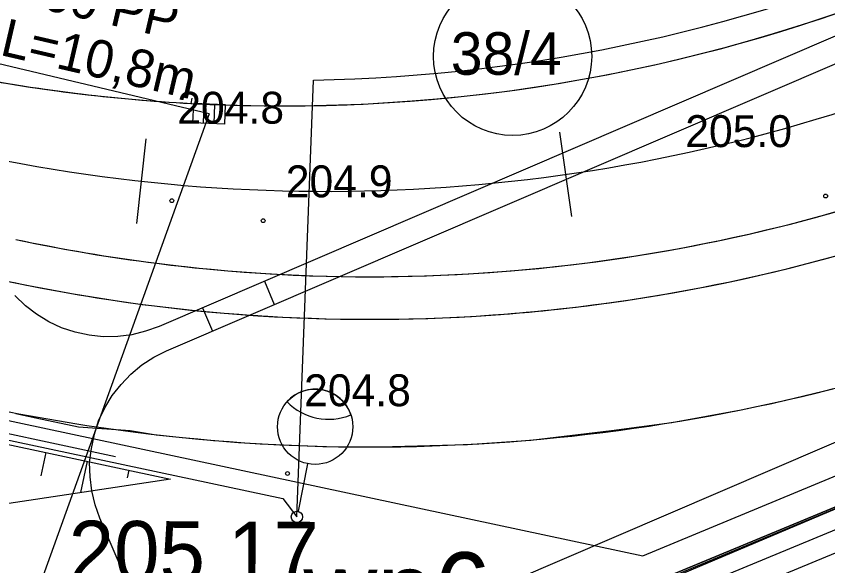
# Model space of a CAD drawing. Extents: x 6512606 to 6513347, y 6022524 to 6022728.
# Drawn here: x 6512813.48 to 6512832.56, y 6022573.02 to 6022585.94 of the extents above; entities that cross this region are included whole.
import ezdxf

# ---------------------------------------------------------------- set-up
doc = ezdxf.new("R2010")
doc.units = 0
for name, color, linetype in [('20', 7, 'Continuous'), ('211-numer działki ewidencyjnej', 7, 'Continuous'), ('217-kontur klasyfikacyjny', 7, 'Continuous'), ('218-kontur użytku gruntowego', 7, 'Continuous'), ('219-działka ewidencyjna', 7, 'Continuous'), ('4', 7, 'Continuous'), ('6', 7, 'Continuous'), ('Default', 7, 'Continuous'), ('E_OSW_KABLE', 7, 'Continuous'), ('E_OSW_LAMPA', 7, 'Continuous'), ('kolor_kostka_bet', 7, 'Continuous'), ('kolor_sc_rowerowa', 7, 'Continuous'), ('Level 47', 7, 'Continuous'), ('Level 60', 7, 'Continuous'), ('maxp_bariera_ochronna', 7, 'Continuous'), ('maxp_inst_energ', 7, 'Continuous'), ('maxp_kan_deszczowa', 7, 'Continuous'), ('maxp_kratki', 7, 'Continuous'), ('maxp_krawężnik', 7, 'Continuous'), ('maxp_obrzeże', 7, 'Continuous'), ('maxp_os', 7, 'Continuous'), ('maxp_ramka_2', 7, 'Continuous'), ('maxp_skarpa', 7, 'Continuous'), ('ogrodzenie trwałe', 7, 'Continuous'), ('pikieta naturalna', 7, 'Continuous'), ('pikieta naturalna-Atr2', 7, 'Continuous'), ('punkt wysokościowy naturalny', 7, 'Continuous'), ('punkt wysokościowy naturalny-Atr2', 7, 'Continuous'), ('urządzenie techniczne projektowane lub w budowie (sieć kanalizacyjna) - powierzchnia - ob. projektowany', 7, 'Continuous')]:
    doc.layers.add(name, color=color, linetype=linetype)

# ---------------------------------------------------------------- blocks, each defined once
blk = doc.blocks.new('PW01')
at = {"layer": 'Default'}
blk.add_circle((0, 0), 0.45, dxfattribs=at)

msp = doc.modelspace()

# ---------------------------------------------------------------- linework, layer by layer
at = {"layer": '20'}
msp.add_line((6512818.017, 6022583.64), (6512813.949, 6022572.326), dxfattribs=at)
at = {"layer": '217-kontur klasyfikacyjny'}
msp.add_lwpolyline([(6512825.22, 6022571.29), (6512855.78, 6022583.95)], dxfattribs=at)
at = {"layer": '218-kontur użytku gruntowego'}
for points in [[(6512825.22, 6022571.29), (6512855.78, 6022583.95)], [(6512855.78, 6022583.95), (6512825.22, 6022571.29)]]:
    msp.add_lwpolyline(points, dxfattribs=at)
at = {"layer": '219-działka ewidencyjna'}
msp.add_lwpolyline([(6512825.22, 6022571.29), (6512855.78, 6022583.95)], dxfattribs=at)
at = {"layer": '4'}
msp.add_lwpolyline([(6512825.22, 6022571.29), (6512855.78, 6022583.95)], dxfattribs=at)
at = {"layer": '6'}
msp.add_circle((6512825.152, 6022584.993), 1.859, dxfattribs=at)
at = {"layer": 'E_OSW_KABLE'}
msp.add_line((6512820.082, 6022574.17), (6512820.469, 6022584.435), dxfattribs=at)
msp.add_lwpolyline([(6512791.895, 6022580.179), (6512792.146, 6022580.477), (6512819.749, 6022574.599), (6512820.082, 6022574.17)], dxfattribs=at)
msp.add_arc((6512819.75, 6022623.828), 39.4, 271.0457, 293.7363, dxfattribs=at)
at = {"layer": 'E_OSW_LAMPA'}
msp.add_line((6512820.334, 6022575.413), (6512820.109, 6022574.3), dxfattribs=at)
for centre, radius in [((6512820.511, 6022576.288), 0.885), ((6512820.082, 6022574.17), 0.132)]:
    msp.add_circle(centre, radius, dxfattribs=at)
for centre, radius, start, end in [((6512820.511, 6022576.288), 0.885, 18.4482, 138.4482), ((6512820.825, 6022577.825), 1.362, 224.2189, 292.6775)]:
    msp.add_arc(centre, radius, start, end, dxfattribs=at)
at = {"layer": 'kolor_kostka_bet'}
msp.add_lwpolyline([(6512773.05, 6022582.65), (6512780.7, 6022581.02), (6512806.2, 6022572.11), (6512806.62, 6022563.51), (6512855.78, 6022583.95)], dxfattribs=at)
msp.add_lwpolyline([(6512773.05, 6022582.65), (6512780.7, 6022581.02), (6512806.2, 6022572.11), (6512806.62, 6022563.51), (6512855.78, 6022583.95)], dxfattribs=at)
for centre, radius, start, end in [((6512819.75, 6022623.828), 40, 270.7527, 293.397), ((6512819.75, 6022623.828), 40, 270.7527, 293.397), ((6512819.75, 6022623.828), 40, 257.9783, 263.418), ((6512819.75, 6022623.828), 40, 258.9864, 263.418), ((6512819.75, 6022623.828), 40, 263.418, 270.7527), ((6512819.75, 6022623.828), 40, 263.418, 270.7527), ((6512821.802, 6022619.813), 40, 257.9783, 293.3967), ((6512821.802, 6022619.813), 40, 257.9783, 293.3967), ((6512821.802, 6022619.813), 41, 257.9783, 293.3967), ((6512821.802, 6022619.813), 44, 262.7977, 293.3967), ((6512821.802, 6022619.813), 44, 257.9787, 262.7977)]:
    msp.add_arc(centre, radius, start, end, dxfattribs=at)
at = {"layer": 'kolor_sc_rowerowa'}
for radius, start, end in [(41, 257.9783, 293.397), (44, 262.7977, 293.3967), (44, 257.9787, 262.7977)]:
    msp.add_arc((6512821.802, 6022619.813), radius, start, end, dxfattribs=at)
at = {"layer": 'Level 60'}
for points in [[(6512826.252, 6022583.207), (6512826.533, 6022581.227)], [(6512816.529, 6022583.052), (6512816.311, 6022581.064)]]:
    msp.add_lwpolyline(points, dxfattribs=at)
at = {"layer": 'maxp_bariera_ochronna'}
msp.add_line((6512753.108, 6022588.943), (6512815.82, 6022575.589), dxfattribs=at)
at = {"layer": 'maxp_inst_energ'}
for p, q in [((6512747.273, 6022590.493), (6512828.214, 6022573.256)), ((6512828.214, 6022573.256), (6512855.354, 6022584.531))]:
    msp.add_line(p, q, dxfattribs=at)
at = {"layer": 'maxp_kan_deszczowa'}
msp.add_line((6512818.017, 6022583.64), (6512807.831, 6022586.066), dxfattribs=at)
msp.add_lwpolyline([(6512813.474, 6022576.599), (6512813.947, 6022576.499), (6512814.946, 6022576.286), (6512814.946, 6022576.286), (6512816.16, 6022576.199), (6512816.77, 6022576.101), (6512817.776, 6022575.997), (6512818.055, 6022575.972), (6512818.711, 6022575.921), (6512819.683, 6022575.864), (6512820.777, 6022575.825), (6512822.027, 6022575.813), (6512824.089, 6022575.872), (6512825.577, 6022575.975), (6512827.474, 6022576.199), (6512828.891, 6022576.387), (6512830.523, 6022576.686), (6512831.542, 6022576.904), (6512832.682, 6022577.179)], dxfattribs=at)
at = {"layer": 'maxp_kratki'}
for p, q in [((6512817.636, 6022583.433), (6512817.655, 6022583.883)), ((6512817.636, 6022583.433), (6512817.655, 6022583.883)), ((6512818.404, 6022583.851), (6512817.655, 6022583.883)), ((6512818.404, 6022583.851), (6512817.655, 6022583.883)), ((6512817.886, 6022583.423), (6512817.905, 6022583.873)), ((6512817.886, 6022583.423), (6512817.905, 6022583.873)), ((6512818.135, 6022583.412), (6512818.155, 6022583.861)), ((6512818.135, 6022583.412), (6512818.155, 6022583.861)), ((6512818.384, 6022583.401), (6512818.404, 6022583.851)), ((6512818.384, 6022583.401), (6512818.404, 6022583.851)), ((6512818.384, 6022583.401), (6512817.636, 6022583.433)), ((6512818.384, 6022583.401), (6512817.636, 6022583.433))]:
    msp.add_line(p, q, dxfattribs=at)
at = {"layer": 'maxp_krawężnik'}
for centre, start, end in [((6512819.75, 6022623.828), 266.9005, 293.397), ((6512819.75, 6022623.828), 258.9864, 266.9005), ((6512821.802, 6022619.813), 262.7977, 293.397), ((6512821.802, 6022619.813), 257.9783, 262.7977)]:
    msp.add_arc(centre, 40, start, end, dxfattribs=at)
at = {"layer": 'maxp_obrzeże'}
msp.add_line((6512817.613, 6022584.009), (6512817.587, 6022583.887), dxfattribs=at)
for radius, start, end in [(41, 262.7977, 293.397), (41, 257.9783, 262.7977), (44, 262.7977, 293.397), (44, 257.9787, 262.7977)]:
    msp.add_arc((6512821.802, 6022619.813), radius, start, end, dxfattribs=at)
at = {"layer": 'maxp_os'}
msp.add_arc((6512820.776, 6022621.82), 40, 257.9783, 293.397, dxfattribs=at)
at = {"layer": 'maxp_ramka_2'}
for points in [[(6512856.423, 6022583.675), (6512826.273, 6022571.185), (6512822.563, 6022569.637), (6512806.155, 6022562.774)], [(6512805.691, 6022562.037), (6512822.756, 6022569.175), (6512826.465, 6022570.723), (6512855.56, 6022582.776)]]:
    msp.add_lwpolyline(points, dxfattribs=at)
at = {"layer": 'maxp_skarpa'}
for p, q in [((6512753.056, 6022588.699), (6512817.11, 6022575.058)), ((6512814.176, 6022575.683), (6512814.059, 6022575.133)), ((6512815.154, 6022575.475), (6512814.998, 6022574.741)), ((6512816.132, 6022575.267), (6512816.093, 6022575.083)), ((6512817.11, 6022575.058), (6512812.885, 6022574.424))]:
    msp.add_line(p, q, dxfattribs=at)
at = {"layer": 'ogrodzenie trwałe'}
msp.add_lwpolyline([(6512818.46, 6022560.27), (6512812.53, 6022565.9), (6512821.8, 6022569.74), (6512835.02, 6022575.32), (6512844.28, 6022579.16), (6512845.12, 6022578.38)], dxfattribs=at)
at = {"layer": 'urządzenie techniczne projektowane lub w budowie (sieć kanalizacyjna) - powierzchnia - ob. projektowany'}
for points in [[(6512848.68, 6022592.32), (6512816.84, 6022578.64), (6512816.52, 6022578.53), (6512816.2, 6022578.45), (6512815.87, 6022578.41), (6512815.53, 6022578.4), (6512815.2, 6022578.44), (6512814.87, 6022578.51), (6512814.55, 6022578.61), (6512814.25, 6022578.75), (6512813.96, 6022578.93), (6512813.7, 6022579.13), (6512813.45, 6022579.37)], [(6512816.32, 6022572.12), (6512815.45, 6022574.14), (6512815.34, 6022574.45), (6512815.26, 6022574.78), (6512815.22, 6022575.11), (6512815.21, 6022575.45), (6512815.25, 6022575.78), (6512815.32, 6022576.11), (6512815.42, 6022576.43), (6512815.57, 6022576.73), (6512815.74, 6022577.02), (6512815.95, 6022577.28), (6512816.18, 6022577.52), (6512816.44, 6022577.74), (6512816.72, 6022577.92), (6512817.02, 6022578.07), (6512848.86, 6022591.74)], [(6512852.09, 6022584.23), (6512820.25, 6022570.56)], [(6512819.32, 6022579.71), (6512819.55, 6022579.16)], [(6512817.86, 6022579.08), (6512818.1, 6022578.53)]]:
    msp.add_lwpolyline(points, dxfattribs=at)

# ---------------------------------------------------------------- block references
at = {"layer": 'pikieta naturalna', "xscale": 0.1, "yscale": 0.10000000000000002}
for p in [(6512832.51, 6022581.71), (6512817.14, 6022581.6), (6512819.86, 6022575.19)]:
    msp.add_blockref('PW01', p, dxfattribs=at)
at = {"layer": 'punkt wysokościowy naturalny', "xscale": 0.1, "yscale": 0.10000000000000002}
msp.add_blockref('PW01', (6512819.29, 6022581.13), dxfattribs=at)

# ---------------------------------------------------------------- texts
at = {"layer": '211-numer działki ewidencyjnej'}
msp.add_text('38/4', height=1, dxfattribs=at).set_placement((6512823.7, 6022584.56))
at = {"layer": '4'}
msp.add_text('38/4', height=1, dxfattribs=at).set_placement((6512823.7, 6022584.56))
at = {"layer": 'Level 47'}
for s, height, rotation, p in [('160 PP', 0.8847, 346.919, (6512813.405, 6022586.263)), ('L=10,8m', 0.8847, 346.919, (6512813.074, 6022585.031)), ('205,17', 1.4377, 359.7281, (6512814.711, 6022572.642)), ('wp6', 1.7971, 359.7281, (6512820.23, 6022571.557))]:
    msp.add_text(s, height=height, rotation=rotation, dxfattribs=at).set_placement(p)
at = {"layer": 'pikieta naturalna-Atr2'}
for s, p in [('204.8', (6512817.27, 6022583.41)), ('205.0', (6512829.21, 6022582.86)), ('204.8', (6512820.25, 6022576.77))]:
    msp.add_text(s, height=0.75, dxfattribs=at).set_placement(p)
at = {"layer": 'punkt wysokościowy naturalny-Atr2'}
msp.add_text('204.9', height=0.75, dxfattribs=at).set_placement((6512819.82, 6022581.68))

doc.saveas('drawing.dxf')
